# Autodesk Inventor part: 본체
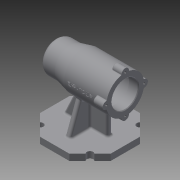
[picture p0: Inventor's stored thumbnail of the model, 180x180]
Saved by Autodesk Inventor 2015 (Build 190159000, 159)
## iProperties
Created: 2019-12
Part Number: 본체
Material: 일반
Document SubType Name: Modeling
Designer: 1021563
Density: 1 g/cm^3
Appearance: 기본값
Mass: 268.815 g
Surface Area: 714.551 cm^2
Volume: 268.815 cm^3
Author: 1021563
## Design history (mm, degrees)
sketch "스케치1"
  geometry: L1 (56, -23.196)-(23.196, -56); L2 (23.196, -56)-(-23.196, -56); L3 (-23.196, -56)-(-56, -23.196); L4 (-56, -23.196)-(-56, 23.196); L5 (-56, 23.196)-(-23.196, 56); L6 (-23.196, 56)-(23.196, 56); L7 (23.196, 56)-(56, 23.196); L8 (56, 23.196)-(56, -23.196); 3 further points
  constraints: 16 end point, 1 midpoint, 17 other
extrude "돌출1" new body sketch "스케치1" distance "d1" = 10; taper "d2" = 0 deg
sketch "스케치2"
  geometry: L1 (56, -23.196)-(56, 23.196) reference; L2 (23.196, 56)-(-23.196, 56) reference; L3 (-56, 23.196)-(-56, -23.196) reference; L4 (-23.196, -56)-(23.196, -56) reference; L5 (-38, -4)-(31, -4); L6 (31, -4)-(31, 4); L7 (31, 4)-(-38, 4); L8 (-38, 4)-(-38, -4); L9 (-4, -36)-(4, -36); L10 (4, -36)-(4, 36); L11 (4, 36)-(-4, 36); L12 (-4, 36)-(-4, -36); 1 further point
  constraints: 16 end point, 4 parallel, 2 horizontal, 2 perpendicular
  dimensions: "d3" = 4 distance from line of L12 point (0, 0); "d4" = 8 distance between parallel lines of L10 L12; "d5" = 4 distance from line of L7 point (0, 0); "d6" = 8 distance between parallel lines of L5 L7; "d7" = 25 distance between parallel lines of L1 L6; "d8" = 18 distance between parallel lines of L8 L3; "d9" = 20 distance between parallel lines of L4 L9; "d10" = 20 distance between parallel lines of L11 L2
extrude "돌출2" join sketch "스케치2" distance "d11" = 70; taper "d12" = 0 deg
sketch "스케치3"
  geometry: L1 (23.196, -56)-(56, -23.196) reference; L2 (56, 23.196)-(23.196, 56) reference; L3 (-23.196, 56)-(-56, 23.196) reference; L4 (-56, -23.196)-(-23.196, -56) reference; C1 r 5 at (-39.598, -39.598); C2 r 5 at (39.598, -39.598); C3 r 5 at (39.598, 39.598); C4 r 5 at (-39.598, 39.598); 1 further point
  constraints: 4 centre point, 4 midpoint
  dimensions: "d13" = 10 diameter of C1; "d14" = 10 diameter of C2; "d15" = 10 diameter of C3; "d16" = 10 diameter of C4
extrude "돌출3" cut sketch "스케치3" stored distance "d17" = 10 (= d14); taper "d18" = 0 deg
feature "면 기울기1" dims angle "d19" = 20 deg
feature "면 기울기2" dims angle "d20" = 25 deg
sketch "스케치4"
  geometry: L1 (-31, 80)-(5.358, 80) reference; L2 (5.358, 80)-(38, 10) reference; L3 (38, 10)-(56, 10) reference; L4 (56, 10)-(56, 0) reference; L5 (56, 0)-(-56, 0) reference; L6 (-56, 0)-(-56, 10) reference; L7 (-56, 10)-(-31, 10) reference; L8 (-31, 10)-(-31, 80) reference; L9 (11, 110)-(-56, 110); L10 (-56, 110)-(-56, 80); L11 (-56, 80)-(56, 80); L12 (56, 80)-(56, 105); L13 (56, 105)-(31, 105); L14 (11, 110)-(31, 105); 3 further points
  constraints: 12 end point, 2 horizontal, 2 midpoint, 2 parallel, 1 collinear, 1 perpendicular, 1 vertical alignment
  dimensions: "d21" = 112 distance between parallel lines of L10 L12; "d23" = 45 distance from line of L9.start L12; "d24" = 25 distance of L13.end L12.end; "d25" = 30 distance of L9.end L10.end; "d26" = 25 distance of L11.end L12.end
revolve "회전1" sketch "스케치4" stored, may be unused: angle "d27" = 90 deg
sketch "스케치5"
  geometry: C1 r 30 at (0, 0) reference; C2 r 21 at (0, 0); 1 further point
  constraints: 1 centre point, 1 coincident
  dimensions: "d28" = 42 diameter of C2
extrude "돌출4" cut sketch "스케치5" distance "d29" = 15; taper "d30" = 0 deg
sketch "스케치6"
  geometry: C1 r 21 at (0, 0) reference; C2 r 24 at (0, 0); 1 further point
  constraints: 1 centre point, 1 coincident
  dimensions: "d31" = 48 diameter of C2
extrude "돌출5" cut sketch "스케치6" distance "d32" = 54; taper "d33" = 0 deg
sketch "스케치7"
  geometry: C1 r 24 at (0, 0) reference; C2 r 21 at (0, 0); 1 further point
  constraints: 1 centre point, 1 coincident
  dimensions: "d34" = 42 diameter of C2
extrude "돌출6" cut sketch "스케치7" distance "d35" = 12; taper "d36" = 0 deg
sketch "스케치8"
  geometry: C1 r 21 at (0, 0) reference; C2 r 17.5 at (0, 0); 1 further point
  constraints: 1 centre point, 1 coincident
  dimensions: "d37" = 35 diameter of C2
extrude "돌출7" cut sketch "스케치8" distance "d38" = 18; taper "d39" = 0 deg
sketch "스케치9"
  geometry: C1 r 17.5 at (0, 0) reference; C2 r 16 at (0, 0); 1 further point
  constraints: 1 centre point, 1 coincident
  dimensions: "d40" = 32 diameter of C2
extrude "돌출8" cut sketch "스케치9" distance "d41" = 4; taper "d42" = 0 deg
sketch "스케치10"
  geometry: C1 r 16 at (0, 0) reference; C2 r 10.5 at (0, 0); 1 further point
  constraints: 1 centre point, 1 coincident
  dimensions: "d43" = 21 diameter of C2
extrude "돌출9" cut sketch "스케치10" distance "d44" = 3; taper "d45" = 0 deg
fillet "모깎기1" dims "d46" = 0.3
fillet "모깎기2" dims "d47" = 3
chamfer "모따기1" distance "d48" = 1; stored, may be unused: second distance "d49" = 2, angle "d50" = 45 deg
sketch "스케치11"
  geometry: C1 r 6 at (-30, 0); 2 further points
  constraints: 2 horizontal alignment, 1 centre point, 1 other
  dimensions: "d51" = 12 diameter of C1
extrude "돌출10" join sketch "스케치11" distance "d52" = 16; taper "d53" = 0 deg
fillet "모깎기3" dims "d54" = 3
fillet "모깎기4" dims "d55" = 1
sketch "스케치12"
  geometry: A1 r 6 centre (0, 0) between (-0.171, 5.998) and (-0.171, -5.998) reference; 1 further point
hole "구멍1" sketch "스케치12" at (0, 0) diameter "d59" = 3.242; stored, may be unused: countersink angle "d63" = 90 deg, drill point angle "d65" = 118 deg; dims "d60" = 8, "d61" = 4, "d62" = 2, "d64" = 11
fillet "모깎기5" dims "d69" = 3
fillet "모깎기6" dims "d70" = 3
fillet "모깎기7" dims "d71" = 3
fillet "모깎기8" dims "d72" = 10
fillet "모깎기9" dims "d73" = 3
node "작업 평면1"
sketch "스케치13"
  geometry: L1 (33.5, -29.226)-(33.5, -6.771) reference; L2 (33.5, -5.998)-(33.5, 5.998) reference; L3 (-78.5, -15)-(-78.5, 15) reference; L4 (33.5, 29.226)-(33.5, 6.771) reference; 3 further points
  constraints: 1 horizontal alignment, 1 midpoint, 1 other
  dimensions: "d78" = 41 distance from line of L4 point (-7.5, 0)
feature "엠보싱1" sketch "스케치13" dims "d5" = 4, "d6" = 8, "d7" = 25, "d8" = 18, "d76" = 0.5, "d77" = 0
fillet "모깎기10" dims "d79" = 0.3
node "솔리드1"
mirror "대칭1"
mirror "대칭2"
pattern_circular "원형 패턴1" dims "d57" = 360 deg
pattern_circular "원형 패턴2" dims angle "d67" = 360 deg
node "절단 모서리 투영1"
